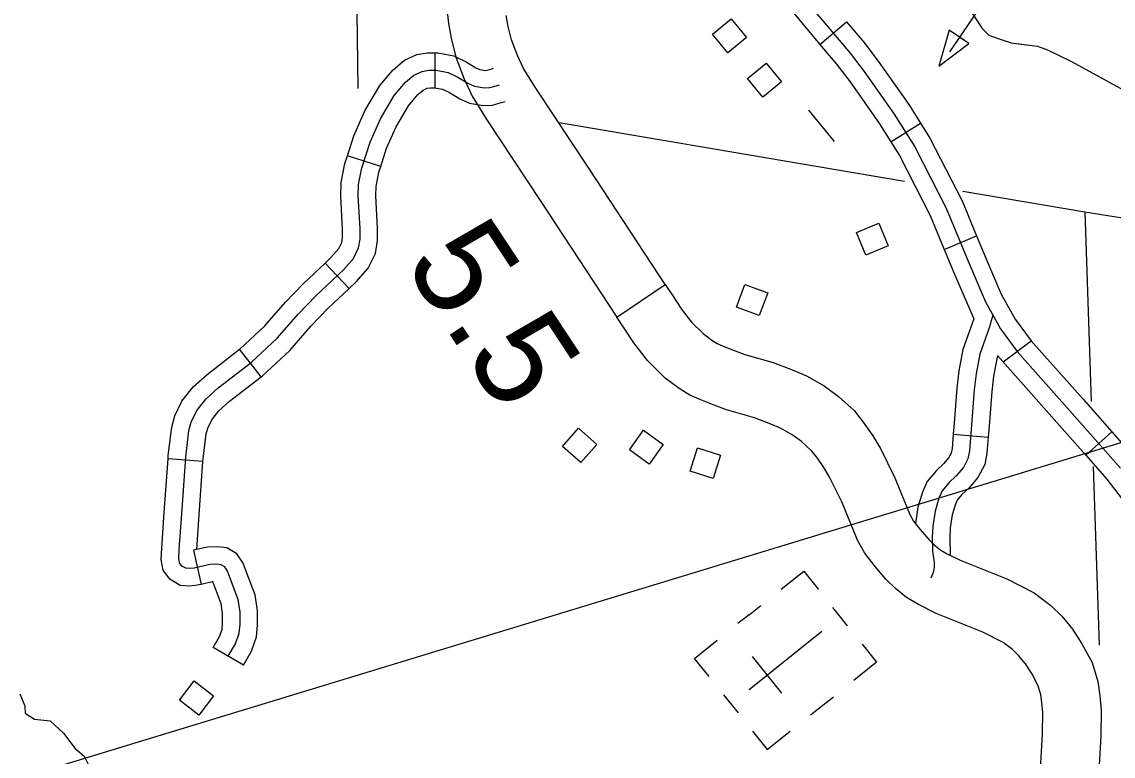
# Model space of a CAD drawing. Extents: x 155 to 3386, y 68 to 2138.
# Drawn here: x 2032.7 to 2166.4, y 927.8 to 1017.8 of the extents above; entities that cross this region are included whole.
import ezdxf

# ---------------------------------------------------------------- set-up
doc = ezdxf.new("R2010")
doc.units = 0
for name, color, linetype in [('2', 7, 'Continuous'), ('Level 10', 7, 'Continuous'), ('Level 32', 7, 'Continuous'), ('Level 35', 7, 'Continuous'), ('Level 4', 7, 'Continuous'), ('Level 43', 7, 'Continuous'), ('Level 48', 7, 'Continuous'), ('Level 5', 7, 'Continuous'), ('Level 56', 7, 'Continuous'), ('Level 57', 7, 'Continuous')]:
    doc.layers.add(name, color=color, linetype=linetype)

msp = doc.modelspace()

# ---------------------------------------------------------------- linework, layer by layer
at = {"layer": '2'}
msp.add_line((1718.72, 829.66), (2409.24, 1039.86), dxfattribs=at)
at = {"layer": 'Level 10'}
for points in [[(2084.69, 1020.6), (2085.01, 1017.58), (2085.33, 1015.76), (2085.9, 1013.45), (2086.88, 1010.86), (2087.91, 1008.66), (2089.69, 1005.79), (2096.23, 995.9), (2105.64, 981.6)], [(2105.64, 981.6), (2111.55, 985.61), (2102.2, 999.84), (2095.7, 1009.64), (2094.2, 1012.07), (2093.46, 1013.64), (2092.73, 1015.57), (2092.33, 1017.22), (2092.09, 1018.57)], [(2157.3, 921.92), (2157.78, 930.57), (2157.81, 933.21), (2157.71, 934.36), (2157.55, 935.4), (2157.21, 936.54), (2156.45, 937.96), (2155.7, 939.13), (2154.85, 940.15), (2154.09, 940.91), (2152.96, 941.77), (2150.48, 943.01), (2144.74, 945.3), (2142.57, 946.41), (2141.13, 947.26), (2139.75, 948.36), (2138.6, 949.51), (2137.23, 951.09), (2136.01, 952.68), (2135.1, 954.28), (2133.18, 958.98), (2131.65, 962.1), (2131, 963.2), (2130.11, 964.45), (2129.48, 965.24), (2128.23, 966.37), (2127.12, 967.2), (2125.68, 968), (2124.51, 968.51), (2122.51, 969.28), (2119.08, 970.25), (2117.55, 970.83), (2115.9, 971.47), (2114.56, 972.06), (2113.26, 972.88), (2111.54, 974.15), (2109.38, 976.28), (2107.72, 978.46), (2106.44, 980.39), (2105.64, 981.6), (2111.55, 985.61)], [(2111.55, 985.61), (2112.4, 984.33), (2113.55, 982.6), (2114.76, 981), (2116.19, 979.6), (2117.28, 978.79), (2117.92, 978.39), (2118.65, 978.07), (2120.11, 977.49), (2121.32, 977.04), (2124.77, 976.06), (2127.22, 975.12), (2128.86, 974.41), (2131.01, 973.2), (2132.77, 971.89), (2134.69, 970.16), (2135.81, 968.76), (2137, 967.08), (2137.94, 965.5), (2139.69, 961.91), (2141.54, 957.41), (2141.98, 956.63), (2142.77, 955.61), (2143.83, 954.38), (2144.51, 953.7), (2145.2, 953.15), (2146.02, 952.67), (2147.69, 951.82), (2153.4, 949.54), (2156.77, 947.85), (2158.81, 946.28), (2160.12, 944.97), (2161.46, 943.37), (2162.6, 941.59), (2163.85, 939.29), (2164.54, 936.96), (2164.81, 935.2), (2164.96, 933.48), (2164.92, 930.33), (2164.43, 921.6)]]:
    msp.add_lwpolyline(points, dxfattribs=at)
at = {"layer": 'Level 32'}
for p, q in [((2130.5, 1015.01), (2133.78, 1017.78)), ((2083.37, 1009.71), (2083.37, 1014)), ((2139.21, 1003.08), (2142.84, 1005.36)), ((2076.7, 1000.04), (2072.62, 1001.37)), ((2145.74, 989.91), (2149.7, 991.55)), ((2072.83, 985.11), (2069.88, 988.22)), ((2152.94, 976.14), (2156.38, 978.69)), ((2062.04, 974.28), (2059.42, 977.67)), ((2146.84, 967.28), (2151.12, 966.92)), ((2163.06, 964.71), (2166.27, 967.55)), ((2054.93, 963.94), (2050.66, 964.25)), ((2053.77, 953.05), (2054.7, 948.86)), ((2059.89, 938.99), (2056.17, 941.13))]:
    msp.add_line(p, q, dxfattribs=at)
for points in [[(2120.87, 1026.37), (2120.96, 1026.28), (2124.07, 1022.78), (2127.87, 1018.13), (2130.5, 1015.01)], [(2129.51, 1019.5), (2134.22, 1013.94), (2135.93, 1011.69), (2139.61, 1006.48), (2142.12, 1002.48), (2145.98, 994.94), (2148.85, 987.99), (2150.77, 983.49), (2152.61, 980.17), (2154.68, 977.39), (2161.13, 970.12), (2167.32, 963.12)], [(2133.78, 1017.78), (2135.89, 1015.28), (2137.66, 1012.96), (2141.39, 1007.66), (2142.84, 1005.36)], [(2130.5, 1015.01), (2132.55, 1012.6), (2134.2, 1010.43), (2137.82, 1005.29), (2139.21, 1003.08)], [(2072.62, 1001.37), (2073.42, 1003.82), (2074.76, 1006.88), (2076.59, 1010), (2078.22, 1011.92), (2079.61, 1013.07), (2081.12, 1013.77), (2082.39, 1014), (2083.37, 1014)], [(2083.37, 1014), (2083.71, 1014), (2085.65, 1013.62), (2087.16, 1012.88), (2088.37, 1012.16), (2088.83, 1011.96), (2089.51, 1011.83), (2089.71, 1011.84), (2090.2, 1011.98), (2090.53, 1012.09)], [(2058.03, 940.06), (2058.9, 941.58), (2059.37, 942.89), (2059.47, 943.96), (2059.47, 945.46), (2059.22, 947.03), (2058.3, 949.52), (2057.94, 950.48), (2057.59, 951.01), (2057.16, 951.26), (2056.63, 951.33), (2055.77, 951.3), (2053.85, 950.87), (2053.28, 950.8), (2052.82, 950.84), (2052.35, 951.12), (2052.07, 951.51), (2051.96, 952.05), (2052.03, 953.15), (2052.32, 957.53), (2052.82, 964.44), (2053.21, 967.71), (2053.49, 968.75), (2054.17, 970.17), (2055.31, 971.59), (2056.8, 972.95), (2060.82, 976.05), (2064.03, 979.04), (2066.63, 982), (2068.76, 984.21), (2072.14, 987.41), (2073.35, 988.8), (2073.99, 990.09), (2074.17, 991.15), (2074.17, 992.44), (2073.96, 996.46), (2074, 997.86), (2074.39, 999.89), (2075.43, 1003.06), (2076.67, 1005.91), (2078.34, 1008.75), (2079.73, 1010.39), (2080.76, 1011.25), (2081.76, 1011.71), (2082.58, 1011.85), (2083.51, 1011.85), (2084.96, 1011.57), (2086.14, 1011), (2087.38, 1010.25), (2088.2, 1009.89), (2089.38, 1009.68), (2090.05, 1009.72), (2090.84, 1009.93), (2091.24, 1010.07)], [(2076.7, 1000.04), (2077.43, 1002.29), (2078.58, 1004.93), (2080.1, 1007.51), (2081.25, 1008.86), (2081.92, 1009.42), (2082.41, 1009.65), (2082.77, 1009.71), (2083.37, 1009.71)], [(2083.37, 1009.71), (2083.3, 1009.71), (2084.28, 1009.52), (2085.12, 1009.11), (2086.4, 1008.34), (2087.58, 1007.83), (2089.24, 1007.53), (2090.4, 1007.59), (2091.47, 1007.88), (2091.94, 1008.04)], [(2142.84, 1005.36), (2143.98, 1003.54), (2147.92, 995.84), (2149.7, 991.55)], [(2139.21, 1003.08), (2140.25, 1001.42), (2144.03, 994.05), (2145.74, 989.91)], [(2069.88, 988.22), (2070.59, 988.9), (2071.56, 990.01), (2071.93, 990.76), (2072.03, 991.33), (2072.03, 992.38), (2071.81, 996.44), (2071.87, 998.1), (2072.32, 1000.43), (2072.62, 1001.37)], [(2072.83, 985.11), (2073.69, 985.93), (2075.15, 987.6), (2076.05, 989.42), (2076.31, 990.98), (2076.31, 992.49), (2076.1, 996.48), (2076.14, 997.62), (2076.47, 999.35), (2076.7, 1000.04)], [(2149.7, 991.55), (2150.82, 988.82), (2152.7, 984.44), (2154.42, 981.34), (2156.38, 978.69)], [(2145.74, 989.91), (2146.87, 987.16), (2149.35, 981.38)], [(2059.42, 977.67), (2059.44, 977.68), (2062.49, 980.53), (2065.05, 983.45), (2067.25, 985.73), (2069.88, 988.22)], [(2062.04, 974.28), (2062.21, 974.41), (2065.57, 977.54), (2068.2, 980.55), (2070.27, 982.69), (2072.83, 985.11)], [(2151.68, 981.86), (2151.24, 980.31), (2150.11, 977.08), (2149.66, 974.68), (2149.42, 972.71), (2149.09, 968.43), (2148.82, 965.23), (2148.64, 964.25), (2148.08, 963.17), (2147.18, 962.15), (2146.34, 961.35), (2145.48, 960.33), (2145.09, 959.43), (2144.61, 957.85), (2144.34, 956.02), (2144.25, 954.65), (2144.31, 952.94), (2144.49, 951.58), (2144.49, 950.92), (2144.37, 950.32), (2144.1, 949.65)], [(2149.35, 981.38), (2148.03, 977.63), (2147.54, 975.01), (2147.29, 972.92), (2146.96, 968.61), (2146.84, 967.28)], [(2156.34, 978.74), (2162.74, 971.55), (2166.27, 967.55)], [(2050.66, 964.25), (2050.68, 964.64), (2051.1, 968.13), (2051.48, 969.5), (2052.34, 971.31), (2053.74, 973.07), (2055.43, 974.59), (2059.42, 977.67)], [(2152.25, 976.89), (2151.78, 974.36), (2151.55, 972.5), (2151.23, 968.26), (2151.12, 966.92)], [(2152.25, 976.89), (2159.53, 968.7), (2163.06, 964.71)], [(2054.93, 963.94), (2054.95, 964.23), (2055.32, 967.3), (2055.51, 968), (2056, 969.03), (2056.87, 970.12), (2058.18, 971.3), (2062.04, 974.28)], [(2146.84, 967.28), (2146.7, 965.52), (2146.59, 964.96), (2146.3, 964.4), (2145.63, 963.64), (2144.78, 962.82), (2143.64, 961.48), (2143.07, 960.17), (2142.51, 958.32), (2142.22, 956.32)], [(2151.12, 966.92), (2150.95, 964.95), (2150.69, 963.54), (2149.85, 961.95), (2148.73, 960.67), (2147.91, 959.88), (2147.31, 959.18), (2147.1, 958.7), (2146.71, 957.38), (2146.47, 955.8), (2146.4, 954.62), (2146.47, 952.44)], [(2166.27, 967.55), (2168.98, 964.49), (2175.76, 955.64)], [(2054.7, 948.86), (2054.22, 948.76), (2053.33, 948.65), (2052.14, 948.74), (2050.87, 949.52), (2050.06, 950.63), (2049.81, 951.9), (2049.9, 953.29), (2050.18, 957.68), (2050.66, 964.25)], [(2054.18, 953.14), (2054.46, 957.38), (2054.93, 963.94)], [(2163.06, 964.71), (2165.67, 961.76), (2172.36, 953.03)], [(2059.89, 938.99), (2060.86, 940.68), (2061.47, 942.43), (2061.62, 943.86), (2061.62, 945.63), (2061.31, 947.57), (2060.31, 950.26), (2059.86, 951.46), (2059.09, 952.61), (2057.87, 953.33), (2056.72, 953.48), (2055.49, 953.43), (2053.77, 953.05)], [(2056.17, 941.13), (2056.95, 942.47), (2057.26, 943.36), (2057.33, 944.07), (2057.33, 945.29), (2057.14, 946.48), (2056.29, 948.77), (2056.14, 949.17), (2056.05, 949.17), (2054.7, 948.86)]]:
    msp.add_lwpolyline(points, dxfattribs=at)
at = {"layer": 'Level 35'}
msp.add_lwpolyline([(2032.5, 935.48), (2033.09, 934), (2033.16, 933.11), (2034.28, 932.37), (2036.21, 932.15), (2037.84, 930.66), (2039.25, 928.81), (2040.36, 927.84), (2041.1, 926.36)], dxfattribs=at)
at = {"layer": 'Level 4'}
for points in [[(2162.95, 994.49), (2163.72, 971.26)], [(2163.98, 963.32), (2164.7, 941.44)]]:
    msp.add_lwpolyline(points, dxfattribs=at)
at = {"layer": 'Level 43'}
for points in [[(2146.77, 1022.49), (2150.4, 1016.95), (2151.19, 1016.16), (2152.34, 1015.72), (2153.92, 1015.22), (2157.16, 1014.79), (2158.39, 1014.36), (2161.34, 1012.92), (2173.71, 1006.15)], [(2154.84, 1015.1), (2157.16, 1014.79), (2158.39, 1014.36), (2161.34, 1012.92), (2165.19, 1010.81)]]:
    msp.add_lwpolyline(points, dxfattribs=at)
at = {"layer": 'Level 5'}
for points in [[(2073.49, 1040.92), (2073.91, 1009.62)], [(2098.58, 1005.43), (2140.86, 998.25)], [(2148.02, 997.03), (2162.95, 994.49)], [(2162.95, 994.49), (2224.22, 984.75)]]:
    msp.add_lwpolyline(points, dxfattribs=at)
at = {"layer": 'Level 56'}
msp.add_lwpolyline([(2146.42, 1014.12), (2160.33, 1034.54), (2153.15, 1044.86)], dxfattribs=at)
for points in [[(2121.53, 1015.87), (2119.24, 1013.97), (2117.34, 1016.26), (2119.63, 1018.16)], [(2125.81, 1010.44), (2123.52, 1008.54), (2121.62, 1010.84), (2123.91, 1012.73)], [(2134.98, 991.97), (2137.74, 993.1), (2138.87, 990.34), (2136.11, 989.21)], [(2124.11, 984.59), (2123.08, 981.8), (2120.28, 982.83), (2121.31, 985.62)], [(2098.98, 965.77), (2100.95, 967.99), (2103.18, 966.01), (2101.21, 963.79)], [(2109.57, 963.6), (2107.16, 965.34), (2108.9, 967.76), (2111.32, 966.02)], [(2115.5, 965.59), (2118.33, 964.68), (2117.43, 961.84), (2114.59, 962.75)], [(2056.23, 935.23), (2054.43, 932.86), (2052.05, 934.67), (2053.86, 937.04)]]:
    msp.add_lwpolyline(points, close=True, dxfattribs=at)
at = {"layer": 'Level 57'}
for p, q in [((2121.84, 945.15), (2123.26, 946.28)), ((2133.88, 943.81), (2132.1, 946.04)), ((2121.84, 945.15), (2120.46, 944.06)), ((2121.83, 936.01), (2130.76, 943.13)), ((2125.84, 935.55), (2122.26, 940.04)), ((2126.29, 939.57), (2126.29, 939.57)), ((2126.29, 939.57), (2126.29, 939.57)), ((2118.69, 935.36), (2120.47, 933.12)), ((2129.37, 932.89), (2132.16, 935.11))]:
    msp.add_line(p, q, dxfattribs=at)
msp.add_lwpolyline([(2148.74, 1015.12), (2146.33, 1016.76), (2145.07, 1012.33)], close=True, dxfattribs=at)
for points in [[(2132.29, 1003.13), (2129.15, 1006.94)], [(2125.75, 948.27), (2128.54, 950.5), (2130.32, 948.26)], [(2116.92, 937.58), (2115.14, 939.81), (2117.93, 942.04)], [(2135.67, 941.56), (2137.45, 939.33), (2134.66, 937.1)], [(2122.26, 930.87), (2124.04, 928.64), (2126.84, 930.87)]]:
    msp.add_lwpolyline(points, dxfattribs=at)

# ---------------------------------------------------------------- texts
at = {"layer": 'Level 48'}
msp.add_text('5.5', height=12.069, rotation=303.3964, dxfattribs=at).set_placement((2079.41, 988.18))

doc.saveas('drawing.dxf')
